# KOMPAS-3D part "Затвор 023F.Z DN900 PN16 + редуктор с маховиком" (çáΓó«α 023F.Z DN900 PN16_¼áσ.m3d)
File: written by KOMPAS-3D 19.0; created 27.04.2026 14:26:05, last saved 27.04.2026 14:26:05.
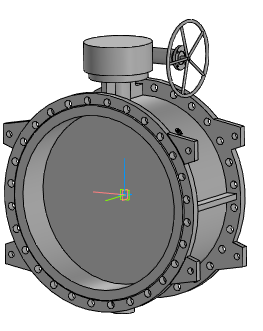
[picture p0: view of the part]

Document properties: Полное имя файла: ..\..\Затвор 023F.Z DN200-DN1600_с маховиком\Затвор 023F.Z DN900 PN16 + редуктор с маховиком.a3d

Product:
- Part/product: Затвор 023F.Z DN900 PN16 + редуктор с маховиком
    Масса: 1061.38

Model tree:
1. Операция без истории:1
